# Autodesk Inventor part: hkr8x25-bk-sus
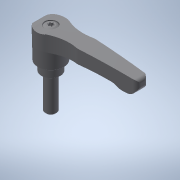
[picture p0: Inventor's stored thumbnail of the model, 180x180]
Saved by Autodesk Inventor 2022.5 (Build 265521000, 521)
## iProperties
Created: 2017-09
Part Number: hkr8x25-bk-sus
Material: 一般
Document SubType Name: Modeling
Designer: imaocorp
Density: 1 g/cm^3
Appearance: 既定
Author: imaocorp
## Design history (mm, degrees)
node "hkr8x25-bk-sus.x_t1"
node "hkr8x25-bk-sus"
node "Base1"
